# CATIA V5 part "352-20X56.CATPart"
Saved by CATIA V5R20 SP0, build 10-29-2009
Part number: 352-20X56
Definition: NONE
Nomenclature: 352-20X56
Source: Unknown
Description: 352-20X56
Bounding box of the stored display mesh (mm): x 0 to 56, y -14 to 14, z -14 to 14
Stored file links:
  C:\Users\Utente\Desktop\IO LAVORO\3D X SITO CF\X SITO\PLASTICA\352\352-20X56.CATPart
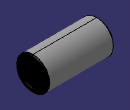
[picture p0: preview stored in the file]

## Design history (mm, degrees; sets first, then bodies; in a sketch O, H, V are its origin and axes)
Body1 "352-20X56" (main body)
  Solid1: solid without history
